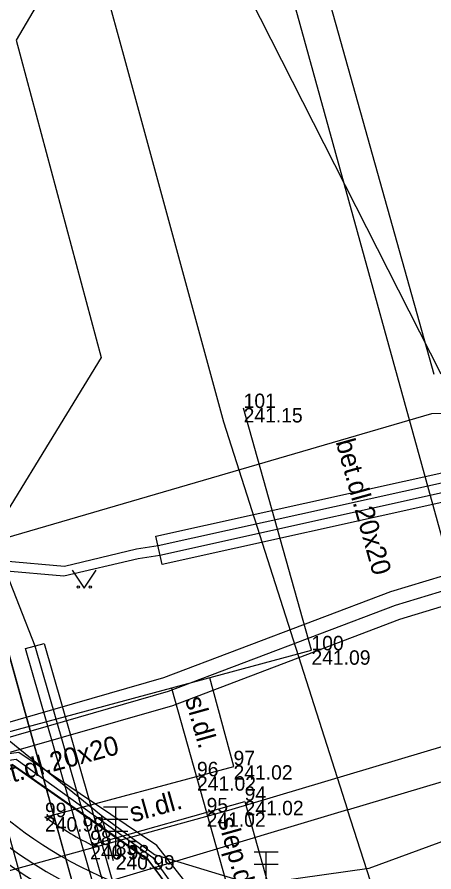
# Model space of a CAD drawing. Extents: x -599432 to -598680, y -1159407 to -1158632.
# Drawn here: x -599018.48 to -599009.82, y -1158877.11 to -1158859.33 of the extents above; entities that cross this region are included whole.
import ezdxf

# ---------------------------------------------------------------- set-up
doc = ezdxf.new("R2010")
doc.units = 0
for name, color, linetype in [('0004 VY - Body podrobné', 7, 'Continuous'), ('0005 VY - Body podrobné - čísla', 7, 'Continuous'), ('0006 VY - Body podrobné - výšky', 7, 'Continuous'), ('0027 ZA - Silnice_cesta zpevněná', 7, 'Continuous'), ('0030 ZA - Chodník', 7, 'Continuous'), ('0031 ZA - Ostatní rozhraní', 7, 'Continuous'), ('0032 TE - Popis povrchu', 7, 'Continuous'), ('0034 ZA - Kultury - značky', 7, 'Continuous'), ('0057 ZA - Doprava - BKOM buňky', 7, 'Continuous'), ('0116 PV - budova převzatá z mapy', 7, 'Continuous'), ('0202 PV - MUNI', 7, 'Continuous'), ('0203 PV - BVK - kanalizace - dešťová přípojka', 7, 'Continuous'), ('0264 PV - TB - parovod mimo provoz', 7, 'Continuous'), ('0304 PV - RWE - STL', 7, 'Continuous'), ('0308 PV - RWE - ochranné pásmo', 7, 'Continuous'), ('0352 PV - EON - NN', 7, 'Continuous'), ('0354 PV - EON - VN', 7, 'Continuous'), ('0367 PV - EON - VN chránička', 7, 'Continuous'), ('0407 PV - TSB - kabelové vedení přibližný zákres', 7, 'Continuous'), ('0454 PV - O2 - kabel zaměřený', 7, 'Continuous'), ('0455 PV - O2 - kabel nezaměřený', 7, 'Continuous'), ('0530 PV - T-mobile - optické kabely', 7, 'Continuous'), ('0552 PV - NETBOX - vedení', 7, 'Continuous'), ('0552 PV - OT VUT', 7, 'Continuous'), ('0553 PV - NETBOX - chranička', 7, 'Continuous'), ('0652 PV - BKOM - kabely bez rozlišení', 7, 'Continuous'), ('0704 PV - ČD - kabely', 7, 'Continuous')]:
    doc.layers.add(name, color=color, linetype=linetype)

msp = doc.modelspace()

# ---------------------------------------------------------------- linework, layer by layer
at = {"layer": '0004 VY - Body podrobné'}
for p, q in [((-599013.77, -1158867.46), (-599013.77, -1158867.46)), ((-599012.36, -1158872.5), (-599012.36, -1158872.5)), ((-599013.98, -1158874.89), (-599013.98, -1158874.89)), ((-599014.74, -1158875.12), (-599014.74, -1158875.12)), ((-599013.75, -1158875.63), (-599013.75, -1158875.63)), ((-599014.54, -1158875.87), (-599014.54, -1158875.87)), ((-599017.9, -1158875.97), (-599017.9, -1158875.97)), ((-599016.96, -1158876.55), (-599016.96, -1158876.55)), ((-599016.43, -1158876.76), (-599016.43, -1158876.76))]:
    msp.add_line(p, q, dxfattribs=at)
at = {"layer": '0027 ZA - Silnice_cesta zpevněná'}
msp.add_arc((-599012.949, -1158868.821), 9.634, 221.457, 284.2368, dxfattribs=at)
at = {"layer": '0030 ZA - Chodník'}
for p, q in [((-599012.36, -1158872.5), (-599013.77, -1158867.46)), ((-599020.59, -1158874.72), (-599012.36, -1158872.5))]:
    msp.add_line(p, q, dxfattribs=at)
at = {"layer": '0031 ZA - Ostatní rozhraní'}
for p, q in [((-599013.974, -1158874.914), (-599014.47, -1158873.069)), ((-599015.267, -1158873.284), (-599013.951, -1158877.966)), ((-599017.9, -1158875.97), (-599013.974, -1158874.914)), ((-599016.943, -1158876.545), (-599013.745, -1158875.647)), ((-599013.745, -1158875.647), (-599013.078, -1158878.02))]:
    msp.add_line(p, q, dxfattribs=at)
for radius, start, end in [(9.199, 218.8468, 263.7494), (9.934, 221.4685, 284.2578), (8.695, 235.2963, 242.6569)]:
    msp.add_arc((-599012.949, -1158868.821), radius, start, end, dxfattribs=at)
at = {"layer": '0034 ZA - Kultury - značky'}
msp.add_lwpolyline([(-599017.334, -1158870.834), (-599017.084, -1158871.209), (-599016.834, -1158870.834)], dxfattribs=at)
for centre in [(-599017.209, -1158871.184), (-599016.959, -1158871.184)]:
    msp.add_circle(centre, 0.025, dxfattribs=at)
at = {"layer": '0057 ZA - Doprava - BKOM buňky'}
for p, q in [((-599016.18, -1158875.76), (-599016.68, -1158875.76)), ((-599016.43, -1158876.76), (-599016.43, -1158875.76)), ((-599016.68, -1158876.01), (-599016.18, -1158876.01)), ((-599016.68, -1158876.26), (-599016.18, -1158876.26)), ((-599016.555, -1158876.76), (-599016.305, -1158876.76)), ((-599013.05, -1158876.7), (-599013.55, -1158876.7)), ((-599013.3, -1158877.7), (-599013.3, -1158876.7)), ((-599013.55, -1158876.95), (-599013.05, -1158876.95))]:
    msp.add_line(p, q, dxfattribs=at)
at = {"layer": '0116 PV - budova převzatá z mapy'}
msp.add_line((-599009.81, -1158866.76), (-599014.86, -1158848.7), dxfattribs=at)
at = {"layer": '0202 PV - MUNI'}
msp.add_lwpolyline([(-599146.637, -1158922.988), (-599125.848, -1158917.745), (-599099.176, -1158910.829), (-599079.1, -1158904.889), (-599063.715, -1158899.846), (-599061.634, -1158898.405), (-599061.066, -1158896.468), (-599061.778, -1158890.969), (-599061.202, -1158889.928), (-599056.191, -1158887.591), (-599053.917, -1158887.479), (-599048.522, -1158885.349), (-599047.385, -1158884.453), (-599040.021, -1158881.203), (-599032.673, -1158878.601), (-599020.545, -1158875.063), (-599018.496, -1158874.767), (-599015.655, -1158876.808), (-599014.942, -1158877.801)], dxfattribs=at)
at = {"layer": '0203 PV - BVK - kanalizace - dešťová přípojka'}
msp.add_line((-599009.663, -1158866.757), (-599015.455, -1158855.336), dxfattribs=at)
msp.add_line((-599009.663, -1158866.757), (-599015.455, -1158855.336), dxfattribs=at)
at = {"layer": '0264 PV - TB - parovod mimo provoz'}
msp.add_line((-599016.185, -1158881.437), (-599027.446, -1158840.907), dxfattribs=at)
at = {"layer": '0304 PV - RWE - STL'}
msp.add_lwpolyline([(-599012.11, -1158899.9), (-599012.24, -1158899.43), (-599012.75, -1158897.13), (-599015.27, -1158888.25), (-599015.46, -1158887.31), (-599017.06, -1158881.76), (-599017.557, -1158880.15), (-599017.73, -1158879.59), (-599017.79, -1158879.41), (-599023.8, -1158857.83), (-599030.992, -1158832.046)], dxfattribs=at)
at = {"layer": '0308 PV - RWE - ochranné pásmo'}
msp.add_lwpolyline([(-599022.837, -1158857.562), (-599016.833, -1158879.118), (-599016.778, -1158879.284), (-599016.602, -1158879.855), (-599016.102, -1158881.474), (-599014.488, -1158887.072), (-599014.297, -1158888.014), (-599011.78, -1158896.885), (-599011.269, -1158899.188), (-599011.146, -1158899.633), (-599011.036, -1158900.032), (-599011.444, -1158900.753), (-599011.843, -1158900.864), (-599012.242, -1158900.974), (-599012.963, -1158900.566), (-599013.074, -1158900.167), (-599013.211, -1158899.672), (-599013.72, -1158897.375), (-599016.243, -1158888.486), (-599016.432, -1158887.548), (-599018.018, -1158882.046), (-599018.512, -1158880.445)], dxfattribs=at)
at = {"layer": '0352 PV - EON - NN'}
msp.add_lwpolyline([(-599021.682, -1158826.616), (-599018.026, -1158839.848), (-599017.168, -1158839.601), (-599017.124, -1158839.718), (-599017.057, -1158839.985), (-599017.919, -1158840.233), (-599016.234, -1158846.334), (-599013.125, -1158857.581), (-599012.296, -1158857.347), (-599012.256, -1158857.465), (-599012.187, -1158857.732), (-599013.017, -1158857.966), (-599008.822, -1158873.141), (-598963.861, -1158860.708)], dxfattribs=at)
at = {"layer": '0354 PV - EON - VN'}
for points in [[(-599030.72, -1158828.814), (-599030.34, -1158830.1), (-599030.07, -1158830.93), (-599028.22, -1158836.83), (-599026.27, -1158844.09), (-599025.41, -1158846.98), (-599023.95, -1158851.91), (-599022.18, -1158857.67), (-599020.86, -1158863.07), (-599019.17, -1158869.69), (-599018.76, -1158870.74), (-599018.11, -1158872.41), (-599013.07, -1158889.93), (-599012.9, -1158891.54), (-599012.14, -1158895.32), (-599011.19, -1158899.2), (-599009.4, -1158905.78), (-599007.56, -1158913), (-599007.02, -1158914.84), (-599006.72, -1158916.06), (-599006.59, -1158917.29)], [(-599068.426, -1158889.707), (-599062.435, -1158887.486), (-599057.559, -1158885.602), (-599053.514, -1158882.536), (-599048.468, -1158879.787), (-599040.575, -1158877.583), (-599039.069, -1158877.224), (-599035.277, -1158875.867), (-599021.599, -1158869.995), (-599019.639, -1158870.482), (-599018.747, -1158870.641), (-599017.491, -1158870.75), (-599015.995, -1158870.391), (-599015.549, -1158870.322), (-599008.216, -1158868.696), (-599005.678, -1158867.267), (-598998.773, -1158865.413), (-598996.328, -1158864.935), (-598994.319, -1158863.656), (-598989.416, -1158862.609), (-598988.122, -1158862.719), (-598986.867, -1158862.571), (-598978.725, -1158860.643), (-598971.459, -1158858.594)], [(-599068.354, -1158889.893), (-599062.365, -1158887.674), (-599057.461, -1158885.778), (-599053.406, -1158882.704), (-599048.392, -1158879.973), (-599040.525, -1158877.777), (-599039.011, -1158877.416), (-599035.203, -1158876.053), (-599021.581, -1158870.205), (-599019.681, -1158870.678), (-599018.773, -1158870.839), (-599017.509, -1158870.95), (-599015.965, -1158870.589), (-599015.511, -1158870.518), (-599008.144, -1158868.884), (-599005.602, -1158867.453), (-598998.727, -1158865.607), (-598996.252, -1158865.125), (-598994.241, -1158863.844), (-598989.404, -1158862.811), (-598988.118, -1158862.921), (-598986.833, -1158862.769), (-598978.675, -1158860.837), (-598971.401, -1158858.786)]]:
    msp.add_lwpolyline(points, dxfattribs=at)
at = {"layer": '0367 PV - EON - VN chránička'}
for p, q in [((-599015.595, -1158870.127), (-599008.245, -1158868.497)), ((-599008.115, -1158869.083), (-599015.465, -1158870.713)), ((-599015.465, -1158870.713), (-599015.595, -1158870.127)), ((-599018.302, -1158872.465), (-599017.918, -1158872.355)), ((-599017.918, -1158872.355), (-599012.873, -1158889.892)), ((-599013.267, -1158889.968), (-599018.302, -1158872.465))]:
    msp.add_line(p, q, dxfattribs=at)
at = {"layer": '0407 PV - TSB - kabelové vedení přibližný zákres'}
for p, q in [((-599009.862, -1158867.58), (-599014.781, -1158869.015)), ((-599009.384, -1158867.567), (-599009.862, -1158867.58)), ((-599014.781, -1158869.015), (-599020.721, -1158870.748))]:
    msp.add_line(p, q, dxfattribs=at)
at = {"layer": '0454 PV - O2 - kabel zaměřený'}
for points in [[(-599017.56, -1158855.4), (-599016.27, -1158860.12)], [(-599016.27, -1158860.12), (-599014.19, -1158867.75), (-599011.61, -1158875.82)], [(-599065.99, -1158901.17), (-599063.3, -1158900.18), (-599061.65, -1158898.45), (-599061.04, -1158896.51), (-599061.91, -1158890.95), (-599061.26, -1158889.87), (-599056.07, -1158887.58), (-599053.91, -1158887.47), (-599052.4, -1158886.85), (-599049.09, -1158885.94), (-599048.46, -1158885.4), (-599047.47, -1158884.55), (-599040.18, -1158881.35), (-599032.72, -1158878.67), (-599020.59, -1158875.17), (-599018.58, -1158874.88), (-599016.36, -1158876.44), (-599015.76, -1158876.86), (-599014.99, -1158877.89), (-599012.08, -1158888.14), (-599011.3, -1158889.38), (-599007.9, -1158892.89), (-599006.6, -1158893.35), (-598996.83, -1158890.81)], [(-599009.82, -1158888.17), (-599010.23, -1158884.21), (-599010.86, -1158878.14), (-599011.61, -1158875.82)]]:
    msp.add_lwpolyline(points, dxfattribs=at)
at = {"layer": '0455 PV - O2 - kabel nezaměřený'}
for points in [[(-599011.61, -1158875.82), (-599007.59, -1158874.62), (-598996.82, -1158872.06), (-598955.03, -1158859.99), (-598940.58, -1158856.31), (-598931.77, -1158853.97)], [(-599011.61, -1158875.82), (-599033.5, -1158882.39)]]:
    msp.add_lwpolyline(points, dxfattribs=at)
at = {"layer": '0530 PV - T-mobile - optické kabely'}
for points in [[(-599015.758, -1158876.853), (-599018.579, -1158874.878)], [(-599014.988, -1158877.884), (-599015.758, -1158876.853)]]:
    msp.add_lwpolyline(points, dxfattribs=at)
at = {"layer": '0552 PV - NETBOX - vedení'}
msp.add_lwpolyline([(-599006.06, -1158869.51), (-599006.06, -1158869.51), (-599007.15, -1158869.17), (-599007.15, -1158869.17), (-599008.89, -1158870.73), (-599009.02, -1158871.08), (-599010.62, -1158871.57), (-599015.34, -1158873.36), (-599021.01, -1158874.99), (-599029.72, -1158877.35), (-599032.35, -1158878.18), (-599038.52, -1158879.88), (-599044.56, -1158881.49), (-599050.4, -1158884.03), (-599052.74, -1158885.29), (-599055.15, -1158886.37), (-599057.94, -1158887.57), (-599060.68, -1158888.43), (-599062.55, -1158889.31)], dxfattribs=at)
at = {"layer": '0552 PV - OT VUT'}
msp.add_lwpolyline([(-599033.74, -1158881.244), (-599014.077, -1158875.825), (-599000.042, -1158871.632), (-598993.234, -1158890.936), (-598991.532, -1158891.542)], dxfattribs=at)
at = {"layer": '0553 PV - NETBOX - chranička'}
for points in [[(-599007.35, -1158868.947), (-599009.145, -1158870.556), (-599009.25, -1158870.837), (-599010.717, -1158871.286), (-599015.435, -1158873.075), (-599021.091, -1158874.701)], [(-599020.929, -1158875.279), (-599015.245, -1158873.645), (-599010.523, -1158871.854), (-599008.79, -1158871.323), (-599008.635, -1158870.904), (-599006.95, -1158869.393), (-599007.35, -1158868.947)]]:
    msp.add_lwpolyline(points, dxfattribs=at)
at = {"layer": '0652 PV - BKOM - kabely bez rozlišení'}
msp.add_line((-599016.73, -1158875.93), (-599016.48, -1158876.87), dxfattribs=at)
for points in [[(-599012.374, -1158857.616), (-599013.19, -1158857.86), (-599018.08, -1158859.1), (-599018.5, -1158859.81), (-599016.73, -1158866.41), (-599019.7, -1158871.25), (-599019.95, -1158872.38), (-599019.48, -1158873.04), (-599018.91, -1158874.17), (-599016.73, -1158875.93), (-599015.62, -1158876.75), (-599013.57, -1158877.37), (-599011.16, -1158877.03), (-599007.55, -1158875.71), (-599007.594, -1158874.617)], [(-599069.54, -1158906.27), (-599056.01, -1158902.46), (-599042.94, -1158898.82), (-599036.88, -1158897.21), (-599035.9, -1158896.65), (-599035.19, -1158895.15), (-599033.43, -1158892.94), (-599032.55, -1158892.85), (-599032.38, -1158891.47), (-599031.43, -1158887.7), (-599033.39, -1158880.98), (-599034.34, -1158877.53), (-599034.11, -1158876.42), (-599020.38, -1158872.59), (-599019.95, -1158872.38), (-599019.48, -1158873.04), (-599018.91, -1158874.17), (-599016.73, -1158875.93), (-599015.62, -1158876.75), (-599013.57, -1158877.37), (-599011.16, -1158877.03), (-599007.55, -1158875.71), (-599006.793, -1158874.464)]]:
    msp.add_lwpolyline(points, dxfattribs=at)
at = {"layer": '0704 PV - ČD - kabely'}
msp.add_lwpolyline([(-598961.2, -1158881.213), (-599006.841, -1158893.881), (-599008, -1158893.389), (-599012.445, -1158888.246), (-599014.794, -1158877.562), (-599015.572, -1158876.562), (-599018.446, -1158874.625), (-599020.43, -1158874.895), (-599032.797, -1158878.387), (-599047.164, -1158884.134), (-599048.64, -1158885.087), (-599049.561, -1158885.388), (-599050.656, -1158886.372), (-599052.371, -1158886.642), (-599054.181, -1158887.388), (-599056.356, -1158887.404), (-599061.221, -1158889.698), (-599062.007, -1158890.833), (-599061.158, -1158896.54), (-599061.825, -1158898.43), (-599063.507, -1158900.144), (-599114.022, -1158914.733)], dxfattribs=at)

# ---------------------------------------------------------------- texts
at = {"layer": '0005 VY - Body podrobné - čísla'}
for s, p in [('101', (-599013.77, -1158867.46)), ('100', (-599012.36, -1158872.5)), ('97', (-599013.98, -1158874.89)), ('96', (-599014.74, -1158875.12)), ('94', (-599013.75, -1158875.63)), ('95', (-599014.54, -1158875.87)), ('99', (-599017.9, -1158875.97)), ('98', (-599016.96, -1158876.55)), ('85', (-599016.43, -1158876.76))]:
    msp.add_text(s, height=0.3, dxfattribs=at).set_placement(p)
at = {"layer": '0006 VY - Body podrobné - výšky'}
for s, p in [('241.15', (-599013.77, -1158867.76)), ('241.09', (-599012.36, -1158872.8)), ('241.02', (-599013.98, -1158875.19)), ('241.02', (-599014.74, -1158875.42)), ('241.02', (-599013.75, -1158875.93)), ('240.98', (-599017.9, -1158876.27)), ('241.02', (-599014.54, -1158876.17)), ('240.98', (-599016.96, -1158876.85)), ('240.99', (-599016.43, -1158877.06))]:
    msp.add_text(s, height=0.3, dxfattribs=at).set_placement(p)
at = {"layer": '0032 TE - Popis povrchu'}
for s, rotation, p in [('bet.dl.20x20', 285.6296, (-599011.859, -1158868.161)), ('sl.dl.', 285.6949, (-599014.99, -1158873.514)), ('bet.dl.20x20', 15.0555, (-599019.147, -1158875.407)), ('sl.dl.', 15.6949, (-599016.077, -1158876.083)), ('slep.dl.', 285.6949, (-599014.313, -1158876.017))]:
    msp.add_text(s, height=0.4, rotation=rotation, dxfattribs=at).set_placement(p)

doc.saveas('drawing.dxf')
